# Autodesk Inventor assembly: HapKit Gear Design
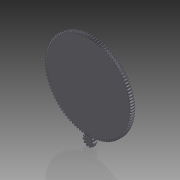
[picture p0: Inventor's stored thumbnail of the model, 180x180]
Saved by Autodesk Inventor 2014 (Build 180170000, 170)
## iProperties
Created: 2015-07
Part Number: HapKit Gear Design
Document SubType Name: Assembly
Designer: Brad Factor
Author: Brad Factor
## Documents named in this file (2)
- D:\Projects\Graduate School\Courses\Haptics\HapKit\HapKit Gear Design.iam
- D:\Projects\Graduate School\Courses\Haptics\HapKit\HapKit Gear Design\Design Accelerator\Spur Gears1.iam
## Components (1 placed, 1 different names)
1. Spur Gears:1 [sub-assembly]
